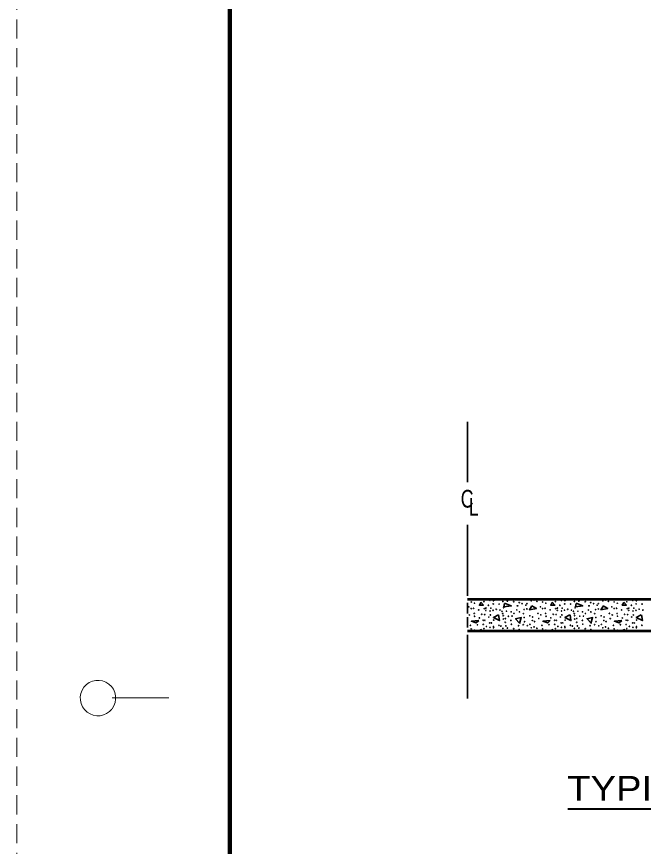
# Model space of a CAD drawing. Extents: x -54 to 626, y -41 to 399.
# Drawn here: x -54.4 to 34, y 75.6 to 192.5 of the extents above; entities that cross this region are included whole.
import ezdxf
from ezdxf.enums import TextEntityAlignment as Align

# ---------------------------------------------------------------- set-up
doc = ezdxf.new("R2010")
doc.units = 0
doc.header["$LTSCALE"] = 0.9
doc.linetypes.add('MEDIUM_DASHED', pattern=[4.5, 3, -1.5])
doc.layers.add('1', color=7, linetype='Continuous', lineweight=35)
doc.layers.add('61', color=7, linetype='Continuous', lineweight=35)

msp = doc.modelspace()

# ---------------------------------------------------------------- linework, layer by layer
at = {"layer": '1', "linetype": 'MEDIUM_DASHED', "lineweight": 13}
msp.add_line((-54.3422, 398.7039), (-54.4022, -41.3361), dxfattribs=at)
at = {"layer": '1'}
for p, q in [((9.1902, 126.9283), (9.1902, 135.4283)), ((9.1902, 110.9283), (9.1902, 120.9283)), ((9.1902, 109.9283), (9.1902, 108.4283)), ((9.1902, 107.9283), (9.1902, 106.4283)), ((9.1902, 105.4283), (9.1902, 96.4283)), ((10.9482, 105.9283), (11.0728, 106.1778)), ((11.0728, 106.2177), (11.3477, 105.9283)), ((14.4091, 105.9283), (14.4328, 106.0378)), ((14.4328, 106.0777), (14.8024, 105.9283)), ((21.0282, 105.9283), (21.1528, 106.1778)), ((21.1528, 106.2177), (21.4277, 105.9283)), ((24.4891, 105.9283), (24.5128, 106.0378)), ((24.5128, 106.0777), (24.8824, 105.9283)), ((31.1082, 105.9283), (31.2328, 106.1778)), ((31.2328, 106.2177), (31.5077, 105.9283))]:
    msp.add_line(p, q, dxfattribs=at)
at = {"layer": '1', "lineweight": 53}
for p, q in [((9.1902, 110.4283), (80.6902, 110.4283)), ((80.6902, 105.9283), (9.1902, 105.9283))]:
    msp.add_line(p, q, dxfattribs=at)
at = {"layer": '1', "lineweight": 40}
msp.add_line((23.3503, 80.9192), (113.7321, 80.9192), dxfattribs=at)
at = {"layer": '1'}
for points in [[(11.0728, 110.0177), (11.4528, 109.6178), (10.8728, 109.5777), (11.0728, 109.9778)], [(21.1528, 110.0177), (21.5328, 109.6178), (20.9528, 109.5777), (21.1528, 109.9778)], [(31.2328, 110.0177), (31.6128, 109.6178), (31.0328, 109.5777), (31.2328, 109.9778)], [(14.4328, 109.8777), (15.3728, 109.4977), (14.3328, 109.3777), (14.4328, 109.8377)], [(18.2528, 109.4977), (18.9128, 109.1377), (17.9328, 108.9577), (18.2928, 109.5177)], [(24.5128, 109.8777), (25.4528, 109.4977), (24.4128, 109.3777), (24.5128, 109.8377)], [(28.3328, 109.4977), (28.9928, 109.1377), (28.0128, 108.9577), (28.3728, 109.5177)], [(13.5528, 108.2377), (12.8528, 107.8377), (13.7128, 107.4177), (13.5928, 108.2578)], [(16.5328, 107.0378), (16.7728, 107.8377), (15.9928, 107.6778), (16.5528, 107.0777)], [(23.6328, 108.2377), (22.9328, 107.8377), (23.7928, 107.4177), (23.6728, 108.2578)], [(26.6128, 107.0378), (26.8528, 107.8377), (26.0728, 107.6778), (26.6328, 107.0777)], [(33.7128, 108.2377), (33.0128, 107.8377), (33.8728, 107.4177), (33.7528, 108.2578)]]:
    msp.add_lwpolyline(points, dxfattribs=at)
for points in [[(10.7928, 107.4577), (9.7528, 107.3377), (10.4328, 107.0977)], [(20.8728, 107.4577), (19.8328, 107.3377), (20.5128, 107.0977)], [(30.9528, 107.4577), (29.9128, 107.3377), (30.5928, 107.0977)]]:
    msp.add_lwpolyline(points, close=True, dxfattribs=at)
for centre in [(9.7247, 110.0484), (11.5139, 110.0882), (11.8794, 110.4016), (12.3698, 110.2738), (12.8601, 110.3883), (12.8733, 110.2208), (14.1987, 110.128), (14.8348, 110.1678), (15.7228, 110.0749), (16.5047, 109.9689), (18.2011, 110.2075), (18.5987, 110.3353), (18.9963, 110.1412), (19.8047, 110.0484), (21.5939, 110.0882), (21.9594, 110.4016), (22.4498, 110.2738), (22.9401, 110.3883), (22.9533, 110.2208), (24.2787, 110.128), (24.9148, 110.1678), (25.8028, 110.0749), (26.5847, 109.9689), (28.2811, 110.2075), (28.6787, 110.3353), (29.0763, 110.1412), (29.8847, 110.0484), (31.6739, 110.0882), (32.0394, 110.4016), (32.5298, 110.2738), (33.0201, 110.3883), (33.0333, 110.2208), (9.4067, 109.3591), (9.7247, 109.1205), (10.0693, 109.1602), (10.1754, 109.8761), (10.785, 108.9348), (11.5669, 109.1072), (11.7866, 108.8685), (11.7998, 109.1867), (12.1577, 109.5845), (12.383, 108.7757), (12.489, 109.1735), (12.8071, 108.8818), (12.8336, 109.77), (13.2577, 109.0276), (13.6686, 109.7568), (13.7879, 108.9083), (14.0661, 108.736), (14.3047, 109.2397), (14.7023, 108.7493), (16.1601, 108.9215), (16.2264, 109.5049), (16.2794, 109.5049), (16.9023, 109.8098), (17.1939, 108.9746), (17.4192, 109.5977), (17.5782, 109.0674), (17.5783, 109.8098), (19.4867, 109.3591), (19.8047, 109.1205), (20.1493, 109.1602), (20.2554, 109.8761), (20.865, 108.9348), (21.6469, 109.1072), (21.8666, 108.8685), (21.8798, 109.1867), (22.2377, 109.5845), (22.463, 108.7757), (22.569, 109.1735), (22.8871, 108.8818), (22.9136, 109.77), (23.3377, 109.0276), (23.7486, 109.7568), (23.8679, 108.9083), (24.1461, 108.736), (24.3847, 109.2397), (24.7823, 108.7493), (26.2401, 108.9215), (26.3064, 109.5049), (26.3594, 109.5049), (26.9823, 109.8098), (27.2739, 108.9746), (27.4992, 109.5977), (27.6582, 109.0674), (27.6583, 109.8098), (29.5667, 109.3591), (29.8847, 109.1205), (30.2293, 109.1602), (30.3354, 109.8761), (30.945, 108.9348), (31.7269, 109.1072), (31.9466, 108.8685), (31.9598, 109.1867), (32.3177, 109.5845), (32.543, 108.7757), (32.649, 109.1735), (32.9671, 108.8818), (32.9936, 109.77), (33.4177, 109.0276), (33.8286, 109.7568), (33.9479, 108.9083), (9.4597, 108.219), (10.1489, 108.4311), (10.2018, 108.0333), (10.8778, 107.808), (11.2091, 108.325), (11.6275, 108.272), (12.2107, 107.9272), (12.436, 108.219), (14.1722, 108.4178), (14.2384, 108.1129), (14.2517, 107.6356), (14.5433, 107.7019), (14.9674, 108.0333), (15.3517, 108.6564), (15.4842, 108.0599), (15.7625, 108.4311), (16.5312, 108.6432), (17.0746, 108.4045), (17.2072, 107.861), (17.9758, 108.0996), (18.3867, 107.9272), (19.1421, 108.4311), (19.2614, 107.7019), (19.5397, 108.219), (20.2289, 108.4311), (20.2818, 108.0333), (20.9578, 107.808), (21.2891, 108.325), (21.7075, 108.272), (22.2907, 107.9272), (22.516, 108.219), (24.2522, 108.4178), (24.3184, 108.1129), (24.3317, 107.6356), (24.6233, 107.7019), (25.0474, 108.0333), (25.4317, 108.6564), (25.5642, 108.0599), (25.8425, 108.4311), (26.6112, 108.6432), (27.1546, 108.4045), (27.2872, 107.861), (28.0558, 108.0996), (28.4667, 107.9272), (29.2221, 108.4311), (29.3414, 107.7019), (29.6197, 108.219), (30.3089, 108.4311), (30.3618, 108.0333), (31.0378, 107.808), (31.3691, 108.325), (31.7875, 108.272), (32.3707, 107.9272), (32.596, 108.219), (9.6187, 106.7606), (10.6127, 106.8402), (11.4212, 107.4766), (11.4212, 106.8799), (11.6473, 107.461), (11.8794, 106.6016), (12.3432, 107.092), (12.3698, 106.4738), (12.5685, 107.092), (12.8601, 106.5883), (12.8733, 106.4208), (12.8999, 107.4898), (13.642, 106.7738), (13.9203, 106.6546), (14.53, 107.1848), (14.6227, 106.6811), (15.3252, 107.45), (15.3914, 106.9065), (16.4119, 106.6943), (17.0613, 106.8402), (17.2469, 107.2644), (17.6445, 106.6943), (18.0023, 106.8932), (18.2011, 106.4075), (18.3469, 107.4368), (18.5987, 106.5353), (18.665, 107.2909), (19.6987, 106.7606), (20.6927, 106.8402), (21.5012, 107.4766), (21.5012, 106.8799), (21.7273, 107.461), (21.9594, 106.6016), (22.4232, 107.092), (22.4498, 106.4738), (22.6485, 107.092), (22.9401, 106.5883), (22.9533, 106.4208), (22.9799, 107.4898), (23.722, 106.7738), (24.0003, 106.6546), (24.61, 107.1848), (24.7027, 106.6811), (25.4052, 107.45), (25.4714, 106.9065), (26.4919, 106.6943), (27.1413, 106.8402), (27.3269, 107.2644), (27.7245, 106.6943), (28.0823, 106.8932), (28.2811, 106.4075), (28.4269, 107.4368), (28.6787, 106.5353), (28.745, 107.2909), (29.7787, 106.7606), (30.7727, 106.8402), (31.5812, 107.4766), (31.5812, 106.8799), (31.8073, 107.461), (32.0394, 106.6016), (32.5032, 107.092), (32.5298, 106.4738), (32.7285, 107.092), (33.0201, 106.5883), (33.0333, 106.4208), (33.0599, 107.4898), (33.802, 106.7738), (9.7247, 106.2484), (10.1754, 106.0761), (11.5139, 106.2882), (12.8336, 105.97), (13.6686, 105.9568), (14.1987, 106.328), (14.8348, 106.3678), (15.7228, 106.2749), (16.5047, 106.1689), (16.9023, 106.0098), (17.5783, 106.0098), (18.9963, 106.3412), (19.8047, 106.2484), (20.2554, 106.0761), (21.5939, 106.2882), (22.9136, 105.97), (23.7486, 105.9568), (24.2787, 106.328), (24.9148, 106.3678), (25.8028, 106.2749), (26.5847, 106.1689), (26.9823, 106.0098), (27.6583, 106.0098), (29.0763, 106.3412), (29.8847, 106.2484), (30.3354, 106.0761), (31.6739, 106.2882), (32.9936, 105.97), (33.8286, 105.9568)]:
    msp.add_circle(centre, 0.0265, dxfattribs=at)
for centre, start, end in [((13.9203, 110.4546), 262.28656, 277.71344), ((24.0003, 110.4546), 262.28656, 277.71344), ((9.1814, 107.7019), 289.58284, 70.41716)]:
    msp.add_arc(centre, 0.0265, start, end, dxfattribs=at)
at = {"layer": '61', "lineweight": 13}
msp.add_line((-40.9222, 96.5239), (-32.9222, 96.5239), dxfattribs=at)
at = {"layer": '61', "lineweight": 158}
msp.add_lwpolyline([(614.6977, 388.7039), (-24.3422, 388.7039), (-24.3422, -31.3161)], dxfattribs=at)
at = {"layer": '61', "lineweight": 13}
msp.add_arc((-42.9245, 96.5052), 2.5, 322.67175, 321.71615, dxfattribs=at)

# ---------------------------------------------------------------- texts
at = {"layer": '1', "width": 0.75}
for s, p in [('C', (8.2422, 123.3456)), ('L', (9.373, 122.2143))]:
    msp.add_text(s, height=2.5, dxfattribs=at).set_placement(p)
at = {"layer": '1', "width": 1.15}
msp.add_text('TYPICAL SECTION WITH CURBING', height=3.5, dxfattribs=at).set_placement((67.982, 82.0277), align=Align.CENTER)

doc.saveas('drawing.dxf')
